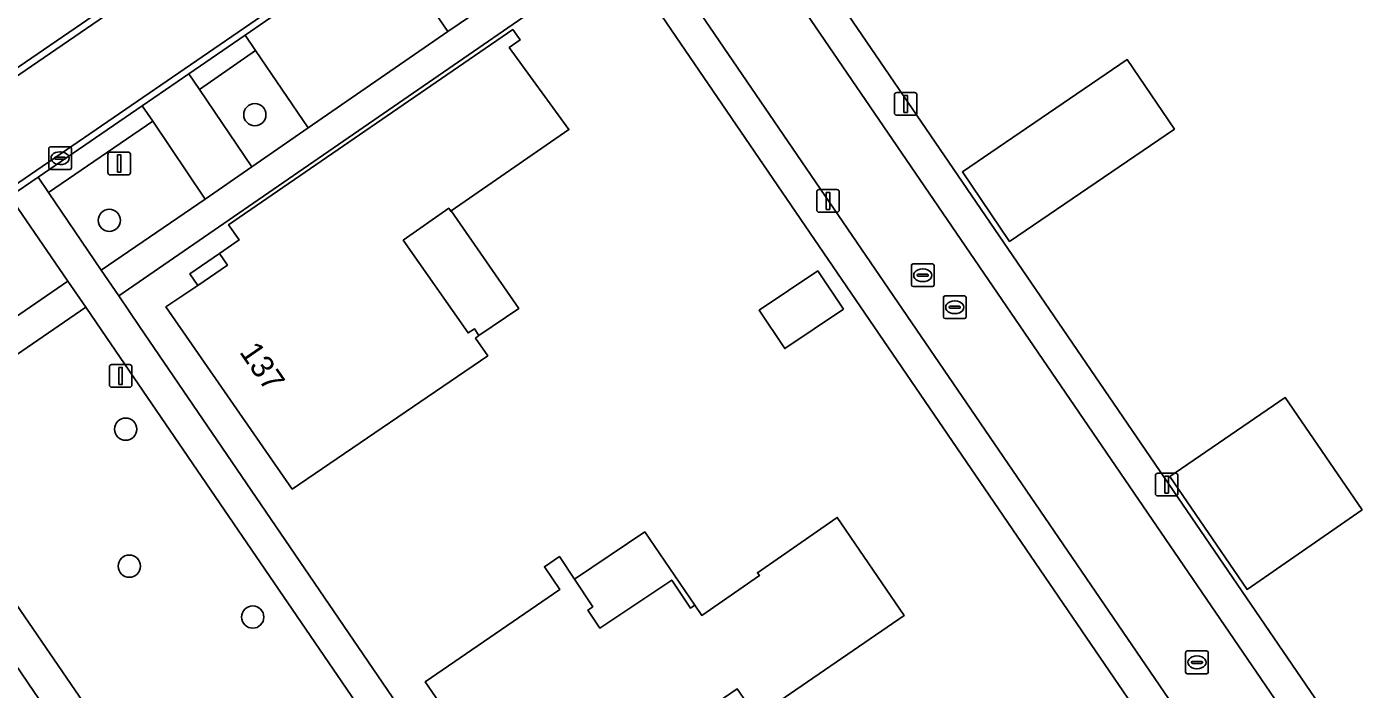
# Model space of a CAD drawing. Extents: x 155275 to 156265, y 382654 to 383635.
# Drawn here: x 155490 to 155548.9, y 383303.7 to 383332.8 of the extents above; entities that cross this region are included whole.
import ezdxf

# ---------------------------------------------------------------- set-up
doc = ezdxf.new("R2010")
doc.units = 0
for name, color, linetype in [('IMGEO_Boom', 7, 'Continuous'), ('IMGEO_Erf', 7, 'Continuous'), ('IMGEO_Groenvoorziening', 7, 'Continuous'), ('IMGEO_Kolk', 7, 'Continuous'), ('IMGEO_Lichtmast', 7, 'Continuous'), ('IMGEO_Pand', 7, 'Continuous'), ('IMGEO_Pand_nummerreeks', 7, 'Continuous'), ('IMGEO_Pand_overbouw', 7, 'Continuous'), ('IMGEO_Parkeervlak_open', 7, 'Continuous'), ('IMGEO_Rijbaan_lokaal_open', 7, 'Continuous'), ('IMGEO_Rioolput', 7, 'Continuous'), ('IMGEO_Voetpad_open', 7, 'Continuous')]:
    doc.layers.add(name, color=color, linetype=linetype)

msp = doc.modelspace()

# ---------------------------------------------------------------- linework, layer by layer
at = {"layer": 'IMGEO_Boom'}
for centre in [(155500.085, 383328.932), (155493.679, 383324.283), (155494.4, 383315.099), (155494.56, 383309.073), (155499.993, 383306.834)]:
    msp.add_circle(centre, 0.489, dxfattribs=at)
at = {"layer": 'IMGEO_Erf'}
for points in [[(155554.524, 383362.222), (155521.756, 383339.814), (155585.616, 383246.401), (155618.427, 383268.752), (155618.124, 383269.195)], [(155518.42, 383332.648), (155516.069, 383336.112), (155494.094, 383320.967), (155495.01, 383319.623), (155509.565, 383298.295), (155558.036, 383227.48), (155580.05, 383242.47)], [(155506.616, 383323.409), (155509.469, 383319.337), (155509.748, 383319.519), (155509.947, 383319.214), (155509.794, 383319.11), (155510.335, 383318.33), (155501.73, 383312.467), (155496.169, 383320.475), (155497.576, 383321.425), (155498.877, 383322.318), (155498.526, 383322.828), (155499.392, 383323.423), (155498.932, 383324.092), (155511.436, 383332.677), (155511.756, 383332.221), (155511.279, 383331.885), (155513.905, 383328.28), (155508.725, 383324.698), (155508.705, 383324.685), (155508.618, 383324.814)], [(155540.551, 383328.302), (155533.297, 383323.361), (155531.218, 383326.413), (155538.473, 383331.353)], [(155525.988, 383320.377), (155523.405, 383318.642), (155522.273, 383320.328), (155524.856, 383322.063)], [(155548.806, 383311.549), (155543.746, 383308.048), (155540.346, 383313.018), (155545.424, 383316.492)], [(155498.922, 383291.025), (155490.365, 383303.561), (155484.692, 383311.871), (155483.519, 383313.595), (155458.608, 383296.58), (155454.563, 383293.76), (155518.365, 383200.253), (155523.731, 383203.931), (155542.221, 383216.713), (155538.669, 383221.857), (155525.357, 383212.738), (155524.015, 383214.705), (155523.982, 383214.682), (155523.259, 383215.732), (155518.011, 383212.12), (155515.657, 383215.542), (155521.261, 383219.398), (155522.097, 383218.189), (155539.024, 383229.787), (155546.127, 383219.41), (155547.42, 383220.262)], [(155522.157, 383302.453), (155521.304, 383303.684), (155513.161, 383298.105), (155511.445, 383300.609), (155510.391, 383299.892), (155507.583, 383303.986), (155513.512, 383308.053), (155512.827, 383309.051), (155513.493, 383309.495), (155514.153, 383308.504), (155514.963, 383307.29), (155514.738, 383307.14), (155515.263, 383306.354), (155518.428, 383308.465), (155519.248, 383307.233), (155519.438, 383307.359), (155519.748, 383306.904), (155522.284, 383308.662), (155522.201, 383308.782), (155525.714, 383311.217), (155528.654, 383306.899)]]:
    msp.add_lwpolyline(points, close=True, dxfattribs=at)
at = {"layer": 'IMGEO_Groenvoorziening'}
msp.add_lwpolyline([(155510.416, 383338.809), (155506.264, 383335.991), (155508.581, 383332.595), (155515.322, 383337.171), (155514.582, 383338.241)], dxfattribs=at)
for points in [[(155500.119, 383331.762), (155497.645, 383330.046), (155499.948, 383326.646), (155502.437, 383328.348)], [(155497.895, 383325.214), (155495.59, 383328.646), (155491.008, 383325.509), (155493.321, 383322.096)], [(155489.301, 383325.333), (155481.111, 383319.724), (155483.675, 383315.993), (155491.858, 383321.607)], [(155493.56, 383319.128), (155492.642, 383320.466), (155484.464, 383314.845), (155485.867, 383312.804), (155497.352, 383296.056), (155505.52, 383301.627)]]:
    msp.add_lwpolyline(points, close=True, dxfattribs=at)
at = {"layer": 'IMGEO_Kolk'}
for p, q in [((155491.09, 383327.519), (155491.942, 383327.519)), ((155491.015, 383326.593), (155491.015, 383327.445)), ((155491.274, 383327.013), (155491.274, 383327.025)), ((155491.712, 383326.976), (155491.314, 383326.976)), ((155491.317, 383327.062), (155491.715, 383327.062)), ((155491.503, 383327.299), (155491.528, 383327.299)), ((155491.758, 383327.025), (155491.758, 383327.013)), ((155492.016, 383327.445), (155492.016, 383326.593)), ((155491.942, 383326.519), (155491.09, 383326.519)), ((155491.526, 383326.739), (155491.501, 383326.739)), ((155530.383, 383320.036), (155530.383, 383320.888)), ((155530.458, 383320.962), (155531.31, 383320.962)), ((155530.642, 383320.456), (155530.642, 383320.468)), ((155530.685, 383320.505), (155531.083, 383320.505)), ((155530.871, 383320.742), (155530.896, 383320.742)), ((155531.126, 383320.468), (155531.126, 383320.456)), ((155531.384, 383320.888), (155531.384, 383320.036)), ((155531.31, 383319.962), (155530.458, 383319.962)), ((155531.08, 383320.419), (155530.682, 383320.419)), ((155530.894, 383320.182), (155530.869, 383320.182)), ((155541.04, 383304.417), (155541.04, 383305.269)), ((155541.115, 383305.343), (155541.967, 383305.343)), ((155542.041, 383305.269), (155542.041, 383304.417)), ((155541.299, 383304.837), (155541.299, 383304.849)), ((155541.737, 383304.8), (155541.339, 383304.8)), ((155541.342, 383304.886), (155541.74, 383304.886)), ((155541.528, 383305.123), (155541.553, 383305.123)), ((155541.783, 383304.849), (155541.783, 383304.837)), ((155541.967, 383304.343), (155541.115, 383304.343)), ((155541.551, 383304.563), (155541.526, 383304.563))]:
    msp.add_line(p, q, dxfattribs=at)
for points in [[(155491.09, 383327.519), (155491.942, 383327.519)], [(155491.015, 383326.593), (155491.015, 383327.445)], [(155492.016, 383327.445), (155492.016, 383326.593)], [(155491.942, 383326.519), (155491.09, 383326.519)], [(155530.383, 383320.036), (155530.383, 383320.888)], [(155530.458, 383320.962), (155531.31, 383320.962)], [(155531.384, 383320.888), (155531.384, 383320.036)], [(155531.31, 383319.962), (155530.458, 383319.962)], [(155541.04, 383304.417), (155541.04, 383305.269)], [(155541.115, 383305.343), (155541.967, 383305.343)], [(155542.041, 383305.269), (155542.041, 383304.417)], [(155541.967, 383304.343), (155541.115, 383304.343)]]:
    msp.add_lwpolyline(points, dxfattribs=at)
for centre, radius, start, end in [((155491.092, 383327.443), 0.0765, 91.55205, 178.44795), ((155491.092, 383327.443), 0.0765, 91.55205, 178.44795), ((155491.94, 383327.443), 0.0765, 1.55205, 88.44795), ((155491.94, 383327.443), 0.0765, 1.55205, 88.44795), ((155491.314, 383327.022), 0.0403, 85.87752, 175.75265), ((155491.311, 383327.012), 0.0366, 178.93798, 274.71019), ((155491.715, 383327.019), 0.043, 264.86636, 352.45326), ((155491.719, 383327.024), 0.0386, 1.73085, 96.63898), ((155491.092, 383326.595), 0.0765, 181.55205, 268.44795), ((155491.092, 383326.595), 0.0765, 181.55205, 268.44795), ((155491.94, 383326.595), 0.0765, 271.55205, 358.44795), ((155491.94, 383326.595), 0.0765, 271.55205, 358.44795), ((155530.46, 383320.886), 0.0765, 91.55205, 178.44795), ((155530.46, 383320.886), 0.0765, 91.55205, 178.44795), ((155530.682, 383320.465), 0.0403, 85.87752, 175.75265), ((155530.679, 383320.455), 0.0366, 178.93798, 274.71019), ((155531.083, 383320.462), 0.043, 264.86636, 352.45326), ((155531.087, 383320.467), 0.0386, 1.73085, 96.63898), ((155531.308, 383320.886), 0.0765, 1.55205, 88.44795), ((155531.308, 383320.886), 0.0765, 1.55205, 88.44795), ((155530.46, 383320.038), 0.0765, 181.55205, 268.44795), ((155530.46, 383320.038), 0.0765, 181.55205, 268.44795), ((155531.308, 383320.038), 0.0765, 271.55205, 358.44795), ((155531.308, 383320.038), 0.0765, 271.55205, 358.44795), ((155541.117, 383305.267), 0.0765, 91.55205, 178.44795), ((155541.117, 383305.267), 0.0765, 91.55205, 178.44795), ((155541.965, 383305.267), 0.0765, 1.55205, 88.44795), ((155541.965, 383305.267), 0.0765, 1.55205, 88.44795), ((155541.339, 383304.846), 0.0403, 85.87752, 175.75265), ((155541.336, 383304.836), 0.0366, 178.93798, 274.71019), ((155541.74, 383304.843), 0.043, 264.86636, 352.45326), ((155541.744, 383304.848), 0.0386, 1.73085, 96.63898), ((155541.117, 383304.419), 0.0765, 181.55205, 268.44795), ((155541.117, 383304.419), 0.0765, 181.55205, 268.44795), ((155541.965, 383304.419), 0.0765, 271.55205, 358.44795), ((155541.965, 383304.419), 0.0765, 271.55205, 358.44795)]:
    msp.add_arc(centre, radius, start, end, dxfattribs=at)
for centre, major_axis, ratio, start_param, end_param in [((155491.502, 383327.019), (-0.387, 0.002), 0.722429, 4.712389, 7.853982), ((155491.527, 383327.019), (-0.39, 0.002), 0.717154, 1.570796, 4.712389), ((155530.87, 383320.462), (-0.387, 0.002), 0.722429, 4.712389, 7.853982), ((155530.895, 383320.462), (-0.39, 0.002), 0.717154, 1.570796, 4.712389), ((155541.527, 383304.843), (-0.387, 0.002), 0.722429, 4.712389, 7.853982), ((155541.552, 383304.843), (-0.39, 0.002), 0.717154, 1.570796, 4.712389)]:
    msp.add_ellipse(centre, major_axis=major_axis, ratio=ratio, start_param=start_param, end_param=end_param, dxfattribs=at)
at = {"layer": 'IMGEO_Lichtmast'}
for p, q in [((155528.329, 383329.905), (155529.119, 383329.905)), ((155529.119, 383329.905), (155528.329, 383329.905)), ((155528.229, 383329.005), (155528.229, 383329.805)), ((155528.229, 383329.805), (155528.229, 383329.005)), ((155529.219, 383329.805), (155529.219, 383329.005)), ((155529.219, 383329.005), (155529.219, 383329.805)), ((155529.119, 383328.905), (155528.329, 383328.905)), ((155528.329, 383328.905), (155529.119, 383328.905)), ((155493.621, 383326.386), (155493.621, 383327.186)), ((155493.621, 383327.186), (155493.621, 383326.386)), ((155493.721, 383327.286), (155494.511, 383327.286)), ((155494.511, 383327.286), (155493.721, 383327.286)), ((155494.611, 383327.186), (155494.611, 383326.386)), ((155494.611, 383326.386), (155494.611, 383327.186)), ((155494.511, 383326.286), (155493.721, 383326.286)), ((155493.721, 383326.286), (155494.511, 383326.286)), ((155524.811, 383324.741), (155524.811, 383325.541)), ((155524.811, 383325.541), (155524.811, 383324.741)), ((155524.911, 383325.641), (155525.701, 383325.641)), ((155525.701, 383325.641), (155524.911, 383325.641)), ((155525.801, 383325.541), (155525.801, 383324.741)), ((155525.801, 383324.741), (155525.801, 383325.541)), ((155525.701, 383324.641), (155524.911, 383324.641)), ((155524.911, 383324.641), (155525.701, 383324.641)), ((155493.683, 383317.042), (155493.683, 383317.842)), ((155493.683, 383317.842), (155493.683, 383317.042)), ((155493.783, 383317.942), (155494.573, 383317.942)), ((155494.573, 383317.942), (155493.783, 383317.942)), ((155494.673, 383317.842), (155494.673, 383317.042)), ((155494.673, 383317.042), (155494.673, 383317.842)), ((155494.573, 383316.942), (155493.783, 383316.942)), ((155493.783, 383316.942), (155494.573, 383316.942)), ((155539.713, 383312.262), (155539.713, 383313.062)), ((155539.713, 383313.062), (155539.713, 383312.262)), ((155539.813, 383313.162), (155540.603, 383313.162)), ((155540.603, 383313.162), (155539.813, 383313.162)), ((155540.703, 383313.062), (155540.703, 383312.262)), ((155540.703, 383312.262), (155540.703, 383313.062)), ((155540.603, 383312.162), (155539.813, 383312.162)), ((155539.813, 383312.162), (155540.603, 383312.162))]:
    msp.add_line(p, q, dxfattribs=at)
for points in [[(155528.649, 383329.78), (155528.799, 383329.78), (155528.799, 383329.03), (155528.649, 383329.03), (155528.649, 383329.78)], [(155494.041, 383327.161), (155494.191, 383327.161), (155494.191, 383326.411), (155494.041, 383326.411), (155494.041, 383327.161)], [(155525.231, 383325.516), (155525.381, 383325.516), (155525.381, 383324.766), (155525.231, 383324.766), (155525.231, 383325.516)], [(155494.103, 383317.817), (155494.253, 383317.817), (155494.253, 383317.067), (155494.103, 383317.067), (155494.103, 383317.817)], [(155540.133, 383313.037), (155540.283, 383313.037), (155540.283, 383312.287), (155540.133, 383312.287), (155540.133, 383313.037)]]:
    msp.add_lwpolyline(points, dxfattribs=at)
for centre, start, end in [((155528.329, 383329.805), 90, 180), ((155528.329, 383329.805), 90, 180), ((155529.119, 383329.805), 0, 90), ((155529.119, 383329.805), 360, 90), ((155528.329, 383329.005), 180, 270), ((155528.329, 383329.005), 180, 270), ((155529.119, 383329.005), 270, 0), ((155529.119, 383329.005), 270, 0), ((155493.721, 383327.186), 90, 180), ((155493.721, 383327.186), 90, 180), ((155494.511, 383327.186), 0, 90), ((155494.511, 383327.186), 360, 90), ((155493.721, 383326.386), 180, 270), ((155493.721, 383326.386), 180, 270), ((155494.511, 383326.386), 270, 0), ((155494.511, 383326.386), 270, 0), ((155524.911, 383325.541), 90, 180), ((155524.911, 383325.541), 90, 180), ((155525.701, 383325.541), 0, 90), ((155525.701, 383325.541), 360, 90), ((155524.911, 383324.741), 180, 270), ((155524.911, 383324.741), 180, 270), ((155525.701, 383324.741), 270, 0), ((155525.701, 383324.741), 270, 0), ((155493.783, 383317.842), 90, 180), ((155493.783, 383317.842), 90, 180), ((155494.573, 383317.842), 0, 90), ((155494.573, 383317.842), 360, 90), ((155493.783, 383317.042), 180, 270), ((155493.783, 383317.042), 180, 270), ((155494.573, 383317.042), 270, 0), ((155494.573, 383317.042), 270, 0), ((155539.813, 383313.062), 90, 180), ((155539.813, 383313.062), 90, 180), ((155540.603, 383313.062), 0, 90), ((155540.603, 383313.062), 360, 90), ((155539.813, 383312.262), 180, 270), ((155539.813, 383312.262), 180, 270), ((155540.603, 383312.262), 270, 0), ((155540.603, 383312.262), 270, 0)]:
    msp.add_arc(centre, 0.1, start, end, dxfattribs=at)
at = {"layer": 'IMGEO_Pand'}
for points in [[(155506.616, 383323.409), (155508.618, 383324.814), (155508.705, 383324.685), (155508.725, 383324.698), (155513.905, 383328.28), (155511.279, 383331.885), (155511.756, 383332.221), (155511.436, 383332.677), (155498.932, 383324.092), (155499.392, 383323.423), (155498.526, 383322.828), (155498.877, 383322.318), (155497.576, 383321.425), (155496.169, 383320.475), (155501.73, 383312.467), (155510.335, 383318.33), (155509.794, 383319.11), (155509.947, 383319.214), (155509.748, 383319.519), (155509.469, 383319.337)], [(155538.473, 383331.353), (155531.218, 383326.413), (155533.297, 383323.361), (155540.551, 383328.302)], [(155525.988, 383320.377), (155524.856, 383322.063), (155522.273, 383320.328), (155523.405, 383318.642)], [(155548.806, 383311.549), (155545.424, 383316.492), (155540.346, 383313.018), (155543.746, 383308.048)], [(155528.654, 383306.899), (155525.714, 383311.217), (155522.201, 383308.782), (155522.284, 383308.662), (155519.748, 383306.904), (155519.438, 383307.359), (155519.248, 383307.233), (155518.428, 383308.465), (155515.263, 383306.354), (155514.738, 383307.14), (155514.963, 383307.29), (155514.153, 383308.504), (155513.493, 383309.495), (155512.827, 383309.051), (155513.512, 383308.053), (155507.583, 383303.986), (155510.391, 383299.892), (155511.445, 383300.609), (155513.161, 383298.105), (155521.304, 383303.684), (155522.157, 383302.453)]]:
    msp.add_lwpolyline(points, close=True, dxfattribs=at)
at = {"layer": 'IMGEO_Pand_overbouw'}
for points in [[(155508.725, 383324.698), (155508.705, 383324.685), (155508.618, 383324.814), (155506.616, 383323.409), (155509.469, 383319.337), (155509.748, 383319.519), (155509.947, 383319.214), (155511.7, 383320.414)], [(155498.526, 383322.828), (155497.229, 383321.935), (155497.576, 383321.425), (155498.877, 383322.318)], [(155519.438, 383307.359), (155517.24, 383310.583), (155514.153, 383308.504), (155514.963, 383307.29), (155514.738, 383307.14), (155515.263, 383306.354), (155518.428, 383308.465), (155519.248, 383307.233)]]:
    msp.add_lwpolyline(points, close=True, dxfattribs=at)
at = {"layer": 'IMGEO_Parkeervlak_open'}
for points in [[(155506.264, 383335.991), (155505.817, 383336.646), (155500.559, 383333.044), (155499.665, 383332.432), (155500.119, 383331.762), (155502.437, 383328.348), (155508.581, 383332.595)], [(155497.645, 383330.046), (155497.181, 383330.731), (155495.133, 383329.328), (155495.59, 383328.646), (155497.895, 383325.214), (155499.948, 383326.646)]]:
    msp.add_lwpolyline(points, close=True, dxfattribs=at)
at = {"layer": 'IMGEO_Rijbaan_lokaal_open'}
for points in [[(155549.095, 383366.65), (155548.143, 383365.998), (155500.38, 383333.268), (155453.502, 383301.158), (155415.989, 383275.504), (155413.779, 383278.713), (155450.858, 383304.106), (155512.791, 383346.508), (155545.973, 383369.225), (155600.872, 383406.808)], [(155580.501, 383393.203), (155517.529, 383350.104), (155512.583, 383346.72), (155508.223, 383343.736), (155450.774, 383304.414), (155450.724, 383304.38), (155449.748, 383303.711), (155441.154, 383297.824), (155413.377, 383278.796)], [(155489.301, 383325.333), (155490.548, 383326.188), (155495.133, 383329.328), (155497.181, 383330.731), (155499.665, 383332.432), (155500.559, 383333.044), (155505.817, 383336.646), (155509.949, 383339.477), (155510.529, 383339.875), (155519.934, 383346.317), (155520.899, 383346.979), (155524.013, 383349.112), (155530.269, 383353.398), (155535.039, 383356.665), (155539.228, 383359.535), (155549.075, 383366.281)], [(155516.069, 383338.699), (155517.287, 383336.916), (155581.249, 383243.309), (155582.508, 383241.467)], [(155585.69, 383243.652), (155584.391, 383245.552), (155520.545, 383338.963)]]:
    msp.add_lwpolyline(points, dxfattribs=at)
msp.add_lwpolyline([(155548.143, 383365.998), (155545.973, 383369.225), (155512.791, 383346.508), (155450.858, 383304.106), (155413.779, 383278.713), (155415.989, 383275.504), (155453.502, 383301.158), (155500.38, 383333.268)], close=True, dxfattribs=at)
at = {"layer": 'IMGEO_Rioolput'}
for p, q in [((155528.975, 383321.443), (155528.975, 383322.295)), ((155529.05, 383322.369), (155529.902, 383322.369)), ((155529.976, 383322.295), (155529.976, 383321.443)), ((155529.234, 383321.863), (155529.234, 383321.875)), ((155529.672, 383321.826), (155529.274, 383321.826)), ((155529.277, 383321.912), (155529.675, 383321.912)), ((155529.463, 383322.149), (155529.488, 383322.149)), ((155529.718, 383321.875), (155529.718, 383321.863)), ((155529.902, 383321.369), (155529.05, 383321.369)), ((155529.486, 383321.589), (155529.461, 383321.589))]:
    msp.add_line(p, q, dxfattribs=at)
for points in [[(155528.975, 383321.443), (155528.975, 383322.295)], [(155529.05, 383322.369), (155529.902, 383322.369)], [(155529.976, 383322.295), (155529.976, 383321.443)], [(155529.902, 383321.369), (155529.05, 383321.369)]]:
    msp.add_lwpolyline(points, dxfattribs=at)
for centre, radius, start, end in [((155529.052, 383322.293), 0.0765, 91.55205, 178.44795), ((155529.052, 383322.293), 0.0765, 91.55205, 178.44795), ((155529.9, 383322.293), 0.0765, 1.55205, 88.44795), ((155529.9, 383322.293), 0.0765, 1.55205, 88.44795), ((155529.274, 383321.872), 0.0403, 85.87752, 175.75265), ((155529.271, 383321.862), 0.0366, 178.93798, 274.71019), ((155529.675, 383321.869), 0.043, 264.86636, 352.45326), ((155529.679, 383321.874), 0.0386, 1.73085, 96.63898), ((155529.052, 383321.445), 0.0765, 181.55205, 268.44795), ((155529.052, 383321.445), 0.0765, 181.55205, 268.44795), ((155529.9, 383321.445), 0.0765, 271.55205, 358.44795), ((155529.9, 383321.445), 0.0765, 271.55205, 358.44795)]:
    msp.add_arc(centre, radius, start, end, dxfattribs=at)
for centre, major_axis, ratio, start_param, end_param in [((155529.462, 383321.869), (-0.387, 0.002), 0.722429, 4.712389, 7.853982), ((155529.487, 383321.869), (-0.39, 0.002), 0.717154, 1.570796, 4.712389)]:
    msp.add_ellipse(centre, major_axis=major_axis, ratio=ratio, start_param=start_param, end_param=end_param, dxfattribs=at)
at = {"layer": 'IMGEO_Voetpad_open'}
for points in [[(155449.748, 383303.711), (155450.724, 383304.38), (155450.774, 383304.414), (155508.223, 383343.736)], [(155514.582, 383338.241), (155515.322, 383337.171), (155508.581, 383332.595), (155502.437, 383328.348), (155499.948, 383326.646), (155497.895, 383325.214), (155493.321, 383322.096), (155494.094, 383320.967), (155516.069, 383336.112)], [(155558.036, 383227.48), (155509.565, 383298.295), (155495.01, 383319.623), (155494.094, 383320.967), (155493.321, 383322.096), (155491.008, 383325.509), (155490.548, 383326.188), (155489.301, 383325.333), (155491.858, 383321.607), (155492.642, 383320.466), (155493.56, 383319.128), (155505.52, 383301.627), (155497.352, 383296.056), (155485.867, 383312.804)], [(155484.692, 383311.871), (155490.365, 383303.561), (155498.922, 383291.025), (155547.42, 383220.262)]]:
    msp.add_lwpolyline(points, dxfattribs=at)
for points in [[(155521.756, 383339.814), (155520.545, 383338.963), (155584.391, 383245.552), (155585.616, 383246.401)], [(155517.287, 383336.916), (155516.069, 383336.112), (155518.42, 383332.648), (155580.05, 383242.47), (155581.249, 383243.309)], [(155500.119, 383331.762), (155499.665, 383332.432), (155497.181, 383330.731), (155497.645, 383330.046)], [(155495.59, 383328.646), (155495.133, 383329.328), (155490.548, 383326.188), (155491.008, 383325.509)], [(155492.642, 383320.466), (155491.858, 383321.607), (155483.675, 383315.993), (155484.464, 383314.845)]]:
    msp.add_lwpolyline(points, close=True, dxfattribs=at)

# ---------------------------------------------------------------- texts
at = {"layer": 'IMGEO_Pand_nummerreeks'}
msp.add_text('137', height=1, rotation=304.57779, dxfattribs=at).set_placement((155499.378, 383318.492))

doc.saveas('drawing.dxf')
